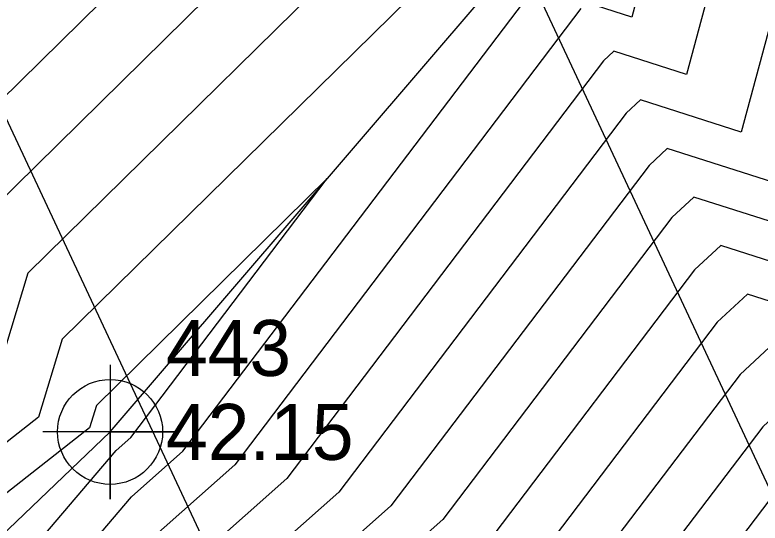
# Model space of a CAD drawing. Extents: x 2090860 to 2091277, y 159470 to 160080.
# Drawn here: x 2091044.64 to 2091077.9, y 159756.86 to 159779.57 of the extents above; entities that cross this region are included whole.
import ezdxf

# ---------------------------------------------------------------- set-up
doc = ezdxf.new("R2010")
doc.units = 0
for name, color, linetype in [('DTM Contours Major', 7, 'Continuous'), ('DTM Contours Minor', 7, 'Continuous'), ('Exist DTM Breakline Underwater', 7, 'Continuous'), ('Exist DTM Breakline Underwater Cogo Elevation', 7, 'Continuous'), ('Exist DTM Breakline Underwater Cogo Number', 7, 'Continuous'), ('Exist DTM Breakline Underwater Cogo Point CELL', 7, 'Continuous'), ('Exist Structure Major Deck Tunnel Box Culvert', 7, 'Continuous')]:
    doc.layers.add(name, color=color, linetype=linetype)

msp = doc.modelspace()

# ---------------------------------------------------------------- linework, layer by layer
at = {"layer": 'DTM Contours Major'}
for points in [[(2091099.517, 159890.851), (2091094.379, 159889.932), (2091085.334, 159880.882), (2091082.516, 159867.927), (2091070.303, 159850.886), (2091072.441, 159844.175), (2091072.201, 159842.82), (2091077.78, 159832.047), (2091073.12, 159814.614), (2091069.924, 159811.606), (2091065.116, 159790.633), (2091059.844, 159786.877), (2091043.696, 159770.983), (2091041.123, 159762.521), (2091029.056, 159753.026), (2091026.145, 159748.964), (2091013.055, 159738.321), (2091004.963, 159727.692), (2091002.968, 159725.938), (2090989.66, 159712.626), (2090981.654, 159705.661)], [(2091087.501, 159783.333), (2091087.769, 159779.288), (2091084.366, 159766.629), (2091076.14, 159769.26), (2091074.973, 159768.174), (2091066.061, 159756.411), (2091053.904, 159745.604), (2091047.888, 159738.533), (2091043.463, 159732.701), (2091041.966, 159731.422), (2091041.639, 159728.479), (2091039.685, 159713.437), (2091038.871, 159704.507), (2091038.64, 159701.617), (2091029.076, 159698.576), (2091027.234, 159702.684), (2091029.528, 159709.044), (2091030.086, 159713.086), (2091034.203, 159729.856), (2091026.977, 159732.23), (2091019.254, 159724.332), (2091013.442, 159718.102), (2090999.017, 159707.674), (2090991.506, 159701.21)], [(2091099.154, 159783.181), (2091099.586, 159776.685), (2091095.347, 159760.92), (2091094.892, 159756.071), (2091093.367, 159756.873), (2091092.489, 159757.381), (2091091.65, 159757.144), (2091080.908, 159760.58), (2091079.033, 159758.835), (2091075.343, 159753.965), (2091056.615, 159737.315), (2091055.277, 159735.743), (2091054.293, 159734.446), (2091049.816, 159730.618), (2091048.96, 159722.933), (2091049.119, 159722.392), (2091048.623, 159719.182), (2091046.944, 159700.747), (2091046.379, 159693.703), (2091023.075, 159686.293)], [(2091075.953, 159781.891), (2091074.613, 159776.904), (2091071.372, 159777.941), (2091070.912, 159777.513), (2091056.779, 159758.858), (2091051.193, 159753.892), (2091040.5, 159741.323), (2091036.181, 159735.631), (2091029.212, 159737.921), (2091015.739, 159724.142), (2091012.177, 159720.324), (2091003.337, 159713.933), (2090990.035, 159702.486)]]:
    msp.add_lwpolyline(points, dxfattribs=at)
at = {"layer": 'DTM Contours Minor'}
for points in [[(2091097.533, 159892.797), (2091089.65, 159891.387), (2091081.841, 159883.574), (2091078.266, 159867.137), (2091067.518, 159852.141), (2091069.963, 159844.468), (2091069.746, 159843.247), (2091076.145, 159830.892), (2091071.957, 159815.224), (2091068.081, 159811.575), (2091063.902, 159793.344), (2091056.602, 159788.144), (2091042.168, 159773.937), (2091038.839, 159762.987), (2091028.464, 159754.823), (2091024.932, 159749.895), (2091013.509, 159740.608), (2091004.14, 159728.3), (2091001.83, 159726.269), (2090989.951, 159714.386), (2090980.303, 159705.993)], [(2091101.501, 159888.904), (2091099.107, 159888.476), (2091088.827, 159878.19), (2091086.766, 159868.717), (2091073.088, 159849.632), (2091074.92, 159843.883), (2091074.655, 159842.393), (2091079.415, 159833.203), (2091074.283, 159814.005), (2091071.767, 159811.636), (2091066.33, 159787.921), (2091063.086, 159785.61), (2091045.223, 159768.028), (2091043.407, 159762.055), (2091029.648, 159751.229), (2091027.357, 159748.032), (2091012.6, 159736.034), (2091005.786, 159727.084), (2091004.106, 159725.607), (2090989.369, 159710.865), (2090983.005, 159705.329)], [(2091066.328, 159784.343), (2091046.751, 159765.073), (2091045.691, 159761.589), (2091030.24, 159749.432), (2091028.57, 159747.101), (2091012.145, 159733.748), (2091006.609, 159726.476), (2091005.244, 159725.276), (2090989.078, 159709.104), (2090984.356, 159704.996)], [(2091090.414, 159783.295), (2091090.724, 159778.637), (2091086.804, 159764.06), (2091077.332, 159767.09), (2091075.988, 159765.839), (2091068.382, 159755.8), (2091054.582, 159743.532), (2091049.736, 159737.835), (2091046.17, 159733.137), (2091043.929, 159731.221), (2091043.438, 159726.812), (2091041.995, 159715.704), (2091040.889, 159703.567), (2091040.574, 159699.638), (2091027.576, 159695.505), (2091025.072, 159701.089), (2091028.191, 159709.733), (2091028.948, 159715.227), (2091032.299, 159728.875), (2091026.418, 159730.808), (2091020.133, 159724.38), (2091013.758, 159717.546), (2090997.937, 159706.109), (2090991.874, 159700.892)], [(2091093.328, 159783.257), (2091093.678, 159777.986), (2091089.243, 159761.491), (2091078.524, 159764.92), (2091077.003, 159763.504), (2091070.702, 159755.188), (2091055.259, 159741.46), (2091051.583, 159737.138), (2091048.878, 159733.573), (2091045.891, 159731.02), (2091045.237, 159725.146), (2091044.305, 159717.971), (2091042.908, 159702.627), (2091042.509, 159697.66), (2091026.075, 159692.434), (2091022.911, 159699.494), (2091026.853, 159710.423), (2091027.811, 159717.368), (2091030.395, 159727.895), (2091025.859, 159729.385), (2091021.012, 159724.428), (2091014.074, 159716.991), (2090996.857, 159704.544), (2090992.242, 159700.573)], [(2091096.241, 159783.219), (2091096.632, 159777.335), (2091091.681, 159758.923), (2091079.716, 159762.75), (2091078.018, 159761.17), (2091073.023, 159754.576), (2091055.937, 159739.388), (2091053.43, 159736.44), (2091051.585, 159734.01), (2091047.854, 159730.819), (2091047.036, 159723.479), (2091046.615, 159720.238), (2091044.926, 159701.687), (2091044.444, 159695.681), (2091024.575, 159689.363), (2091020.749, 159697.899), (2091025.515, 159711.112), (2091026.673, 159719.509), (2091028.491, 159726.914), (2091025.301, 159727.962), (2091021.891, 159724.475), (2091014.39, 159716.435), (2090995.777, 159702.98), (2090992.609, 159700.254)], [(2091072.999, 159782.542), (2091072.174, 159779.473), (2091070.18, 159780.111)], [(2090989.3, 159703.124), (2091005.497, 159717.062), (2091011.545, 159721.435), (2091013.982, 159724.047), (2091030.33, 159740.766), (2091034.328, 159739.452), (2091036.806, 159742.718), (2091049.838, 159758.036), (2091052.138, 159760.081), (2091068.882, 159782.182)], [(2091078.907, 159781.24), (2091077.051, 159774.335), (2091072.564, 159775.771), (2091071.927, 159775.178), (2091059.099, 159758.246), (2091051.871, 159751.82), (2091042.347, 159740.625), (2091037.107, 159733.72), (2091028.653, 159736.498), (2091016.618, 159724.19), (2091012.493, 159719.768), (2091002.257, 159712.368), (2090990.403, 159702.167)], [(2091081.861, 159780.589), (2091079.489, 159771.767), (2091073.756, 159773.601), (2091072.942, 159772.843), (2091061.42, 159757.634), (2091052.549, 159749.748), (2091044.194, 159739.928), (2091038.048, 159731.828), (2091038.042, 159731.823), (2091038.04, 159731.812), (2091035.064, 159708.902), (2091034.835, 159706.388), (2091034.77, 159705.574), (2091032.077, 159704.717), (2091031.558, 159705.874), (2091032.204, 159707.665), (2091032.361, 159708.804), (2091038.011, 159731.817), (2091028.095, 159735.075), (2091017.497, 159724.237), (2091012.809, 159719.213), (2091001.177, 159710.803), (2090990.771, 159701.848)], [(2091069.897, 159779.847), (2091054.458, 159759.469), (2091050.515, 159755.964), (2091038.653, 159742.02), (2091035.254, 159737.542), (2091029.771, 159739.343), (2091014.861, 159724.095), (2091011.861, 159720.879), (2091004.417, 159715.498), (2090989.667, 159702.805)], [(2091084.815, 159779.939), (2091081.928, 159769.198), (2091074.948, 159771.43), (2091073.958, 159770.509), (2091063.74, 159757.023), (2091053.226, 159747.676), (2091046.041, 159739.23), (2091040.755, 159732.265), (2091040.004, 159731.622), (2091039.84, 159730.145), (2091037.374, 159711.17), (2091036.853, 159705.448), (2091036.705, 159703.595), (2091030.576, 159701.647), (2091029.396, 159704.279), (2091030.866, 159708.355), (2091031.224, 159710.945), (2091036.107, 159730.837), (2091027.536, 159733.653), (2091018.376, 159724.285), (2091013.126, 159718.657), (2091000.097, 159709.239), (2090991.138, 159701.529)], [(2090988.932, 159703.443), (2091006.577, 159718.627), (2091011.229, 159721.99), (2091013.103, 159723.999), (2091030.889, 159742.188), (2091033.401, 159741.363), (2091034.959, 159743.415), (2091049.16, 159760.108), (2091049.817, 159760.692), (2091058.581, 159772.26), (2091048.278, 159762.119), (2091047.975, 159761.123), (2091030.832, 159747.635), (2091029.783, 159746.17), (2091011.69, 159731.461), (2091007.432, 159725.867), (2091006.383, 159724.945), (2090988.787, 159707.344), (2090985.707, 159704.664)]]:
    msp.add_lwpolyline(points, dxfattribs=at)
at = {"layer": 'Exist DTM Breakline Underwater'}
msp.add_lwpolyline([(2090988.242, 159704.041), (2091010.175, 159723.841), (2091048.889, 159760.937), (2091068.273, 159783.583), (2091089.722, 159842.139), (2091103.231, 159887.207)], dxfattribs=at)
at = {"layer": 'Exist DTM Breakline Underwater Cogo Point CELL'}
msp.add_lwpolyline([(2091048.889, 159763.937), (2091048.889, 159757.937), (2091048.889, 159760.937), (2091051.889, 159760.937), (2091045.889, 159760.937)], dxfattribs=at)
msp.add_circle((2091048.889, 159760.937), 2.344, dxfattribs=at)
at = {"layer": 'Exist Structure Major Deck Tunnel Box Culvert'}
msp.add_lwpolyline([(2091083.939, 159746.358), (2091062.342, 159736.259), (2091031.248, 159802.748), (2091052.743, 159813.103)], close=True, dxfattribs=at)

# ---------------------------------------------------------------- texts
at = {"layer": 'Exist DTM Breakline Underwater Cogo Elevation'}
msp.add_text('42.15', height=2.5, dxfattribs=at).set_placement((2091051.389, 159759.687))
at = {"layer": 'Exist DTM Breakline Underwater Cogo Number'}
msp.add_text('443', height=2.5, dxfattribs=at).set_placement((2091051.389, 159763.437))

doc.saveas('drawing.dxf')
